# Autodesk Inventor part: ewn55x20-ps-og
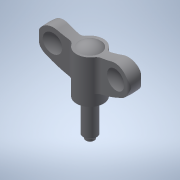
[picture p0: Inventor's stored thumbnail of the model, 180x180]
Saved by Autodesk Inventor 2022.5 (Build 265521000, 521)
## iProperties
Created: 2016-12
Part Number: ewn55x20-ps-og
Material: 一般
Document SubType Name: Modeling
Designer: imaocorp
Density: 1 g/cm^3
Appearance: 既定
Author: imaocorp
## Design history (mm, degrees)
node "ewn55x20-ps-og.x_t1"
node "ewn55x20-ps-og"
node "Base1"
